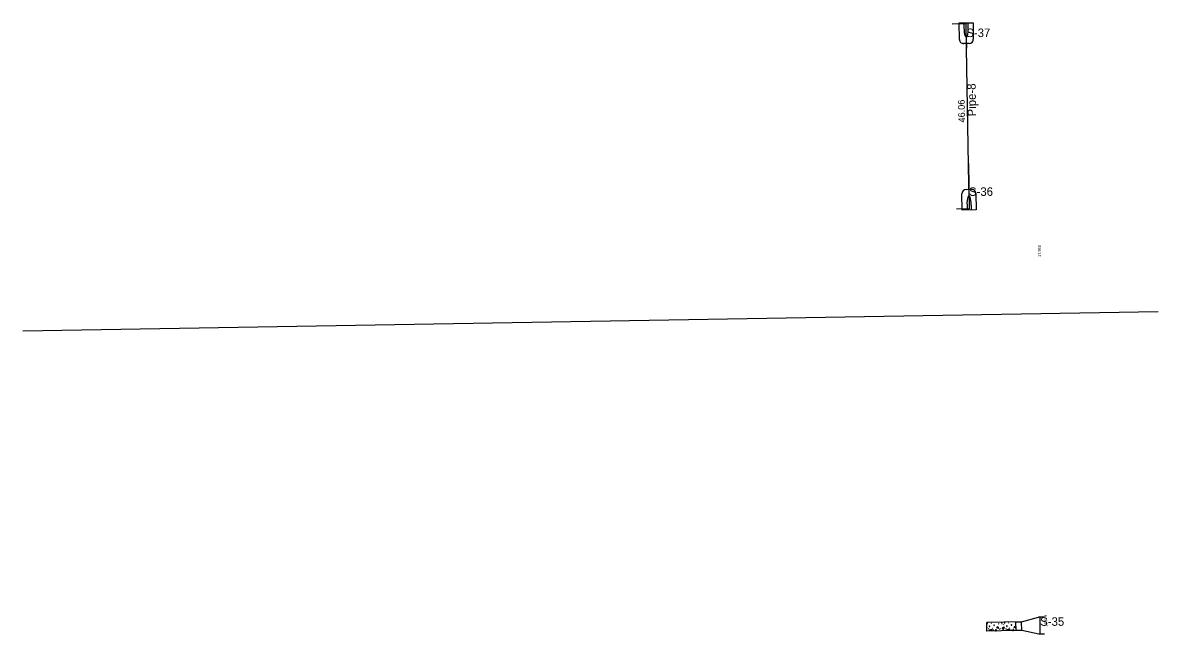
# Model space of a CAD drawing. Extents: x 925371 to 925937, y 853654 to 858024.
# Drawn here: x 925409 to 925809.1, y 856215.1 to 856430.8 of the extents above; entities that cross this region are included whole.
import ezdxf

# ---------------------------------------------------------------- set-up
doc = ezdxf.new("R2010")
doc.units = 0
for name, color, linetype in [('DitchPavt', 7, 'Continuous'), ('GPKDrBack_dp', 7, 'Continuous'), ('GPKDrBottom_dp', 7, 'Continuous'), ('GPKDrCellIns_dp', 7, 'Continuous'), ('GPKDrFront_dp', 7, 'Continuous'), ('GPKDrPipe_dp', 7, 'Continuous'), ('InletClosedFlume', 7, 'Continuous'), ('MES', 7, 'Continuous'), ('Miscellaneous5', 7, 'Continuous'), ('NonPlottingEle_dp', 7, 'Continuous'), ('PipeCulvert', 7, 'Continuous')]:
    doc.layers.add(name, color=color, linetype=linetype)

msp = doc.modelspace()

# ---------------------------------------------------------------- linework, layer by layer
at = {"layer": 'DitchPavt'}
for p, q in [((925760.96, 856219.54), (925748.65, 856219.33)), ((925749.31, 856217), (925749.47, 856217.13)), ((925750.17, 856218.98), (925750.31, 856219.08)), ((925750.57, 856217.24), (925750.73, 856217.34)), ((925751.76, 856216.39), (925751.93, 856216.35)), ((925753.02, 856218.72), (925752.8, 856218.81)), ((925753.18, 856216.8), (925753.33, 856216.9)), ((925753.36, 856217.07), (925753.51, 856217.17)), ((925754.16, 856218.71), (925753.95, 856218.8)), ((925754.63, 856216.76), (925754.43, 856216.85)), ((925754.55, 856218.48), (925754.71, 856218.59)), ((925755.44, 856217.1), (925755.59, 856217.23)), ((925756.29, 856219.09), (925756.43, 856219.18)), ((925756.7, 856217.34), (925756.85, 856217.44)), ((925757.88, 856216.49), (925758.06, 856216.45)), ((925758.97, 856218.89), (925758.92, 856218.91))]:
    msp.add_line(p, q, dxfattribs=at)
for points in [[(925753.71, 856219.42), (925753.71, 856219.4), (925753.74, 856219.29), (925753.85, 856219.25)], [(925753.85, 856219.25), (925754.01, 856219.3), (925754.06, 856219.43)], [(925759.01, 856216.47), (925748.7, 856216.29), (925748.65, 856219.33)], [(925748.68, 856217.62), (925748.74, 856217.65), (925748.68, 856217.49)], [(925748.86, 856218.93), (925748.95, 856218.93), (925748.97, 856219.01), (925748.95, 856219.09), (925748.85, 856219.15), (925748.81, 856219.12), (925748.76, 856219.05), (925748.76, 856218.96), (925748.86, 856218.93)], [(925749.69, 856217.82), (925749.72, 856217.85), (925749.75, 856217.95), (925749.7, 856218.04), (925749.65, 856218.07), (925749.56, 856218.04), (925749.53, 856217.91), (925749.56, 856217.85), (925749.63, 856217.82), (925749.69, 856217.82)], [(925750.13, 856216.32), (925749.62, 856216.57), (925750.41, 856216.89), (925750.47, 856216.32)], [(925751.07, 856216.44), (925751.12, 856216.56), (925751.05, 856216.56), (925750.98, 856216.53), (925751.01, 856216.45), (925751.07, 856216.44)], [(925751.28, 856218.19), (925751.37, 856218.29), (925751.37, 856218.38), (925751.26, 856218.44), (925751.15, 856218.34), (925751.18, 856218.28), (925751.2, 856218.22), (925751.28, 856218.19), (925751.25, 856218.19)], [(925752.05, 856216.35), (925752.12, 856216.44), (925752.12, 856216.52), (925752.12, 856216.69), (925751.93, 856216.76), (925751.76, 856216.71), (925751.71, 856216.6), (925751.71, 856216.48), (925751.76, 856216.39)], [(925752.78, 856217.15), (925752.16, 856217.45), (925752.52, 856217.93), (925752.78, 856217.15)], [(925754.2, 856217.15), (925754.26, 856217.19), (925754.29, 856217.27), (925754.26, 856217.33), (925754.2, 856217.35), (925754.12, 856217.33), (925754.04, 856217.3), (925754.08, 856217.21), (925754.11, 856217.14), (925754.2, 856217.15)], [(925754.58, 856216.96), (925754.29, 856217.49), (925754.86, 856217.75), (925754.58, 856216.96)], [(925754.98, 856219.03), (925755.08, 856219.04), (925755.09, 856219.11), (925755.07, 856219.19), (925754.98, 856219.25), (925754.93, 856219.22), (925754.89, 856219.16), (925754.89, 856219.06), (925754.98, 856219.03)], [(925755.81, 856217.92), (925755.84, 856217.96), (925755.87, 856218.05), (925755.83, 856218.14), (925755.78, 856218.17), (925755.68, 856218.14), (925755.66, 856218.01), (925755.69, 856217.95), (925755.75, 856217.92), (925755.81, 856217.92)], [(925756.25, 856216.42), (925755.74, 856216.67), (925756.53, 856217), (925756.59, 856216.43)], [(925757.2, 856216.54), (925757.24, 856216.67), (925757.18, 856216.67), (925757.1, 856216.63), (925757.13, 856216.55), (925757.2, 856216.54)], [(925757.4, 856218.29), (925757.49, 856218.39), (925757.49, 856218.48), (925757.38, 856218.54), (925757.27, 856218.45), (925757.31, 856218.39), (925757.32, 856218.32), (925757.4, 856218.29), (925757.37, 856218.29)], [(925758.17, 856216.45), (925758.24, 856216.54), (925758.24, 856216.62), (925758.24, 856216.79), (925758.05, 856216.87), (925757.88, 856216.82), (925757.83, 856216.71), (925757.84, 856216.58), (925757.88, 856216.49)], [(925758.9, 856217.26), (925758.29, 856217.56), (925758.64, 856218.03), (925758.9, 856217.26)]]:
    msp.add_lwpolyline(points, dxfattribs=at)
at = {"layer": 'GPKDrBack_dp'}
for p, q in [((925741.37, 856430.76), (925741.37, 856430.76)), ((925742.49, 856364.7), (925742.49, 856364.7)), ((925760.99, 856218.02), (925760.99, 856218.02))]:
    msp.add_line(p, q, dxfattribs=at)
at = {"layer": 'GPKDrBottom_dp'}
for p, q in [((925741.45, 856425.73), (925741.45, 856425.73)), ((925742.4, 856369.73), (925742.4, 856369.73)), ((925767.48, 856218.13), (925767.48, 856218.13))]:
    msp.add_line(p, q, dxfattribs=at)
at = {"layer": 'GPKDrCellIns_dp'}
for p, q in [((925741.45, 856425.73), (925741.45, 856425.73)), ((925742.4, 856369.73), (925742.4, 856369.73)), ((925767.48, 856218.13), (925767.48, 856218.13))]:
    msp.add_line(p, q, dxfattribs=at)
at = {"layer": 'GPKDrFront_dp'}
for p, q in [((925741.49, 856423.44), (925741.49, 856423.44)), ((925742.36, 856372.02), (925742.36, 856372.02)), ((925768.98, 856218.16), (925768.98, 856218.16))]:
    msp.add_line(p, q, dxfattribs=at)
at = {"layer": 'GPKDrPipe_dp'}
for p, q in [((925741.52, 856421.76), (925741.52, 856421.76)), ((925742.34, 856373.7), (925742.34, 856373.7))]:
    msp.add_line(p, q, dxfattribs=at)
at = {"layer": 'InletClosedFlume'}
for p, q in [((925760.96, 856219.54), (925766.93, 856221.12)), ((925761.01, 856216.5), (925760.96, 856219.54)), ((925768.93, 856221.16), (925766.93, 856221.12)), ((925767.54, 856215.13), (925767.43, 856221.13)), ((925767.04, 856215.13), (925761.01, 856216.5)), ((925769.04, 856215.16), (925767.04, 856215.13))]:
    msp.add_line(p, q, dxfattribs=at)
msp.add_lwpolyline([(925761.01, 856216.5), (925759.01, 856216.47), (925758.96, 856219.51), (925760.96, 856219.54)], dxfattribs=at)
at = {"layer": 'MES'}
for p, q in [((925738.91, 856430.71), (925743.83, 856430.8)), ((925739.01, 856424.89), (925738.91, 856430.71)), ((925740.65, 856429), (925740.66, 856430.74)), ((925742.14, 856429.02), (925742.07, 856430.77)), ((925743.83, 856430.8), (925743.92, 856424.98)), ((925742.45, 856423.45), (925740.53, 856423.42)), ((925741.49, 856423.44), (925741.52, 856421.76)), ((925741.41, 856372.01), (925743.32, 856372.04)), ((925742.36, 856372.02), (925742.34, 856373.7)), ((925740.03, 856364.66), (925739.93, 856370.48)), ((925744.85, 856370.57), (925744.95, 856364.75)), ((925744.95, 856364.75), (925740.03, 856364.66)), ((925741.71, 856366.44), (925741.78, 856364.69)), ((925743.21, 856366.46), (925743.19, 856364.72))]:
    msp.add_line(p, q, dxfattribs=at)
for centre, start, end in [((925740.51, 856424.92), 180.9741, 270.9741), ((925742.43, 856424.95), 270.9741, 0.9741), ((925741.43, 856370.51), 90.9741, 180.9741), ((925743.35, 856370.54), 0.9741, 90.9741)]:
    msp.add_arc(centre, 1.5, start, end, dxfattribs=at)
for centre, major_axis in [((925741.4, 856428.73), (0.05, -3)), ((925742.45, 856366.73), (-0.05, 3))]:
    msp.add_ellipse(centre, major_axis=major_axis, ratio=0.25, start_param=4.617261, end_param=7.949056, dxfattribs=at)
at = {"layer": 'Miscellaneous5'}
msp.add_line((925809.11, 856328.86), (925408.98, 856322.06), dxfattribs=at)
at = {"layer": 'NonPlottingEle_dp'}
for points in [[(925741.64, 856414.41), (925741.37, 856430.4), (925736.47, 856430.32)], [(925742.21, 856381.11), (925742.48, 856365.11), (925738.05, 856365.04)]]:
    msp.add_lwpolyline(points, dxfattribs=at)
at = {"layer": 'PipeCulvert'}
msp.add_line((925742.34, 856373.7), (925741.52, 856421.76), dxfattribs=at)

# ---------------------------------------------------------------- texts
at = {"layer": 'NonPlottingEle_dp'}
for s, p in [('S-37', (925741.45, 856425.73)), ('S-36', (925742.4, 856369.73)), ('S-35', (925767.48, 856218.13))]:
    msp.add_text(s, height=3, dxfattribs=at).set_placement(p)
for s, height, p in [('Pipe-8', 3, (925744.93, 856397.78)), ('46.06', 2.4, (925741.03, 856395.64)), ('17.950', 1, (925767.78, 856348.16)), ('17.679', 1, (925769.99, 856217.79))]:
    msp.add_text(s, height=height, rotation=90.9741, dxfattribs=at).set_placement(p)

doc.saveas('drawing.dxf')
